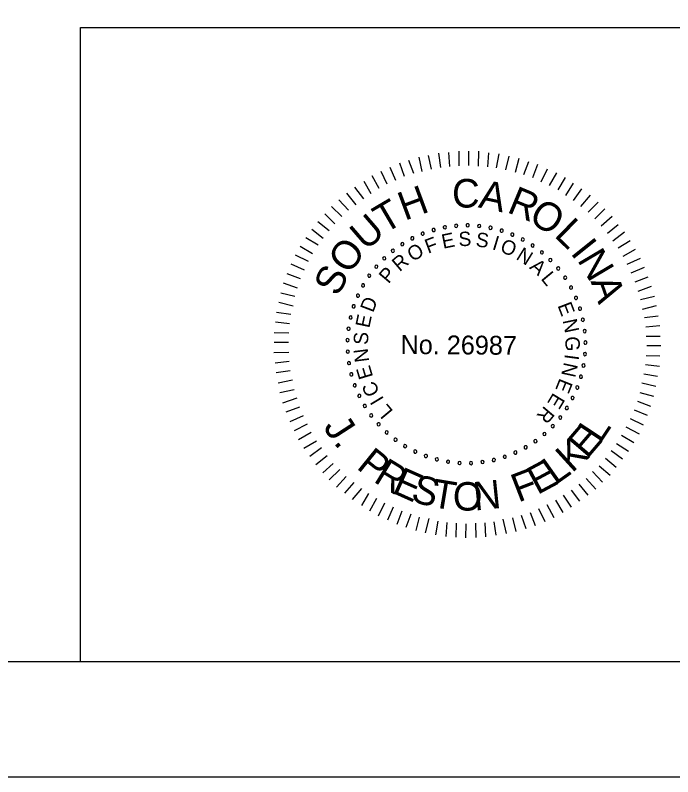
# Model space of a CAD drawing. Extents: x -383 to 3, y -322 to -94.
# Drawn here: x -215.77 to -204.37, y -187.49 to -174.28 of the extents above; entities that cross this region are included whole.
import ezdxf

# ---------------------------------------------------------------- set-up
doc = ezdxf.new("R2010")
doc.units = 0
for name, color, linetype in [('BR_BORDER LINES', 7, 'Continuous'), ('BR_TEXT', 7, 'Continuous'), ('Level 31', 7, 'Continuous')]:
    doc.layers.add(name, color=color, linetype=linetype)

msp = doc.modelspace()

# ---------------------------------------------------------------- linework, layer by layer
at = {"layer": 'BR_BORDER LINES'}
for p, q in [((-214.64, -174.489), (-193.18, -174.489)), ((-214.64, -185.489), (-214.64, -174.489)), ((-297.843, -185.489), (-163.178, -185.489))]:
    msp.add_line(p, q, dxfattribs=at)
at = {"layer": 'BR_TEXT'}
for p, q in [((-208.077, -176.892), (-208.075, -176.634)), ((-207.909, -176.883), (-207.907, -176.636)), ((-207.741, -176.895), (-207.732, -176.637)), ((-208.717, -176.986), (-208.77, -176.742)), ((-208.552, -176.946), (-208.608, -176.709)), ((-208.394, -176.917), (-208.429, -176.673)), ((-208.236, -176.901), (-208.251, -176.657)), ((-207.58, -176.906), (-207.561, -176.663)), ((-207.426, -176.925), (-207.382, -176.681)), ((-207.265, -176.957), (-207.208, -176.721)), ((-207.1, -176.999), (-207.036, -176.756)), ((-209.02, -177.076), (-209.103, -176.842)), ((-208.861, -177.026), (-208.949, -176.795)), ((-206.953, -177.042), (-206.865, -176.813)), ((-206.795, -177.095), (-206.708, -176.862)), ((-209.323, -177.211), (-209.427, -176.987)), ((-209.175, -177.144), (-209.269, -176.92)), ((-206.652, -177.165), (-206.54, -176.942)), ((-206.508, -177.234), (-206.383, -177.012)), ((-209.602, -177.377), (-209.724, -177.16)), ((-209.461, -177.282), (-209.582, -177.065)), ((-206.358, -177.308), (-206.229, -177.093)), ((-209.726, -177.462), (-209.883, -177.258)), ((-206.225, -177.405), (-206.089, -177.19)), ((-206.091, -177.492), (-205.946, -177.291)), ((-209.861, -177.564), (-210.021, -177.363)), ((-205.962, -177.596), (-205.799, -177.398)), ((-209.993, -177.662), (-210.159, -177.482)), ((-205.836, -177.696), (-205.663, -177.519)), ((-210.11, -177.771), (-210.287, -177.594)), ((-205.723, -177.807), (-205.55, -177.634)), ((-210.228, -177.894), (-210.402, -177.724)), ((-205.611, -177.932), (-205.421, -177.765)), ((-210.328, -178.02), (-210.526, -177.864)), ((-205.502, -178.06), (-205.316, -177.907)), ((-210.432, -178.153), (-210.63, -177.993)), ((-205.407, -178.194), (-205.21, -178.038)), ((-210.519, -178.269), (-210.735, -178.137)), ((-205.319, -178.312), (-205.109, -178.183)), ((-210.617, -178.416), (-210.832, -178.287)), ((-205.231, -178.46), (-205.017, -178.335)), ((-210.686, -178.552), (-210.912, -178.441)), ((-210.756, -178.699), (-210.985, -178.598)), ((-205.16, -178.598), (-204.929, -178.49)), ((-205.089, -178.746), (-204.862, -178.648)), ((-210.826, -178.853), (-211.059, -178.766)), ((-205.022, -178.901), (-204.795, -178.817)), ((-210.876, -179.014), (-211.122, -178.923)), ((-204.968, -179.063), (-204.738, -178.976)), ((-210.925, -179.158), (-211.168, -179.098)), ((-210.954, -179.326), (-211.204, -179.262)), ((-204.928, -179.207), (-204.688, -179.151)), ((-204.895, -179.376), (-204.654, -179.316)), ((-210.996, -179.47), (-211.24, -179.437)), ((-204.862, -179.52), (-204.625, -179.491)), ((-211.015, -179.634), (-211.261, -179.605)), ((-204.836, -179.685), (-204.592, -179.66)), ((-211.026, -179.792), (-211.284, -179.79)), ((-204.831, -179.843), (-204.59, -179.845)), ((-211.034, -179.957), (-211.285, -179.955)), ((-204.822, -180.008), (-204.578, -180.01)), ((-211.029, -180.129), (-211.286, -180.133)), ((-204.833, -180.18), (-204.593, -180.189)), ((-211.02, -180.283), (-211.267, -180.312)), ((-204.841, -180.334), (-204.598, -180.367)), ((-211.004, -180.448), (-211.248, -180.484)), ((-204.87, -180.499), (-204.634, -180.538)), ((-210.964, -180.606), (-211.215, -180.659)), ((-204.906, -180.656), (-204.666, -180.713)), ((-210.938, -180.775), (-211.182, -180.831)), ((-204.942, -180.824), (-204.702, -180.885)), ((-210.891, -180.923), (-211.139, -181.006)), ((-204.984, -180.971), (-204.755, -181.059)), ((-210.845, -181.077), (-211.079, -181.161)), ((-205.04, -181.125), (-204.814, -181.213)), ((-210.777, -181.226), (-211.008, -181.334)), ((-210.71, -181.37), (-210.937, -181.489)), ((-205.11, -181.272), (-204.884, -181.384)), ((-210.642, -181.519), (-210.859, -181.644)), ((-205.183, -181.416), (-204.954, -181.538)), ((-205.257, -181.563), (-205.045, -181.692)), ((-210.547, -181.667), (-210.765, -181.792)), ((-210.462, -181.784), (-210.663, -181.93)), ((-205.347, -181.71), (-205.139, -181.839)), ((-210.361, -181.919), (-210.561, -182.075)), ((-205.437, -181.826), (-205.243, -181.975)), ((-210.262, -182.054), (-210.439, -182.217)), ((-205.535, -181.959), (-205.351, -182.118)), ((-210.146, -182.158), (-210.326, -182.338)), ((-205.645, -182.092), (-205.458, -182.258)), ((-210.031, -182.279), (-210.2, -182.463)), ((-205.874, -182.313), (-205.704, -182.5)), ((-205.76, -182.194), (-205.589, -182.377)), ((-209.901, -182.383), (-210.064, -182.57)), ((-206.002, -182.415), (-205.842, -182.605)), ((-209.768, -182.487), (-209.928, -182.678)), ((-209.645, -182.574), (-209.77, -182.782)), ((-206.133, -182.517), (-205.99, -182.71)), ((-209.505, -182.664), (-209.63, -182.879)), ((-206.402, -182.69), (-206.277, -182.907)), ((-206.268, -182.602), (-206.135, -182.812)), ((-209.368, -182.744), (-209.477, -182.967)), ((-209.221, -182.814), (-209.319, -183.037)), ((-206.699, -182.835), (-206.591, -183.059)), ((-206.554, -182.768), (-206.432, -182.992)), ((-209.068, -182.884), (-209.155, -183.11)), ((-208.91, -182.933), (-209.001, -183.166)), ((-207.002, -182.949), (-206.918, -183.183)), ((-206.843, -182.902), (-206.759, -183.13)), ((-208.766, -182.983), (-208.823, -183.219)), ((-208.602, -183.011), (-208.662, -183.258)), ((-208.444, -183.057), (-208.484, -183.29)), ((-208.287, -183.076), (-208.306, -183.323)), ((-208.129, -183.087), (-208.131, -183.335)), ((-207.961, -183.099), (-207.963, -183.343)), ((-207.792, -183.09), (-207.787, -183.338)), ((-207.631, -183.081), (-207.616, -183.329)), ((-207.476, -183.065), (-207.437, -183.299)), ((-207.315, -183.022), (-207.262, -183.27)), ((-207.15, -182.996), (-207.09, -183.233))]:
    msp.add_line(p, q, dxfattribs=at)
for centre, start, end in [((-208.323, -177.957), 10.6038, 190.6038), ((-208.323, -177.957), 190.6038, 10.6038), ((-208.126, -177.93), 5.0653, 185.0653), ((-208.126, -177.93), 185.0653, 5.0653), ((-207.926, -177.923), 359.5268, 179.5268), ((-207.926, -177.923), 179.5268, 359.5268), ((-207.727, -177.934), 173.9884, 353.9884), ((-207.727, -177.934), 353.9884, 173.9884), ((-207.531, -177.965), 168.4499, 348.4499), ((-207.531, -177.965), 348.4499, 168.4499), ((-208.706, -178.067), 21.6807, 201.6807), ((-208.706, -178.067), 201.6807, 21.6807), ((-208.517, -178.003), 16.1422, 196.1422), ((-208.517, -178.003), 196.1422, 16.1422), ((-207.338, -178.015), 162.9114, 342.9114), ((-207.338, -178.015), 342.9114, 162.9114), ((-207.15, -178.083), 157.373, 337.373), ((-207.15, -178.083), 337.373, 157.373), ((-209.06, -178.248), 32.7576, 212.7576), ((-208.887, -178.149), 27.2191, 207.2191), ((-208.887, -178.149), 207.2191, 27.2191), ((-206.97, -178.169), 151.8345, 331.8345), ((-206.97, -178.169), 331.8345, 151.8345), ((-209.223, -178.364), 38.2961, 218.2961), ((-209.223, -178.364), 218.2961, 38.2961), ((-209.06, -178.248), 212.7576, 32.7576), ((-206.8, -178.272), 146.2961, 326.2961), ((-206.8, -178.272), 326.2961, 146.2961), ((-209.373, -178.495), 43.8345, 223.8345), ((-209.373, -178.495), 223.8345, 43.8345), ((-206.639, -178.39), 140.7576, 320.7576), ((-206.639, -178.39), 320.7576, 140.7576), ((-209.511, -178.639), 49.373, 229.373), ((-209.511, -178.639), 229.373, 49.373), ((-206.492, -178.524), 135.2191, 315.2191), ((-206.492, -178.524), 315.2191, 135.2191), ((-206.357, -178.671), 129.6807, 309.6807), ((-206.357, -178.671), 309.6807, 129.6807), ((-209.633, -178.796), 54.9114, 234.9114), ((-209.633, -178.796), 234.9114, 54.9114), ((-206.238, -178.831), 124.1422, 304.1422), ((-206.238, -178.831), 304.1422, 124.1422), ((-209.74, -178.964), 60.4499, 240.4499), ((-209.74, -178.964), 240.4499, 60.4499), ((-206.135, -179.001), 118.6038, 298.6038), ((-206.135, -179.001), 298.6038, 118.6038), ((-209.83, -179.142), 65.9884, 245.9884), ((-209.83, -179.142), 245.9884, 65.9884), ((-206.048, -179.181), 113.0653, 293.0653), ((-206.048, -179.181), 293.0653, 113.0653), ((-209.903, -179.328), 71.5268, 251.5268), ((-209.903, -179.328), 251.5268, 71.5268), ((-205.979, -179.368), 107.5268, 287.5268), ((-205.979, -179.368), 287.5268, 107.5268), ((-209.957, -179.52), 77.0653, 257.0653), ((-209.957, -179.52), 257.0653, 77.0653), ((-205.929, -179.561), 101.9884, 281.9884), ((-205.929, -179.561), 281.9884, 101.9884), ((-209.993, -179.716), 82.6038, 262.6038), ((-209.993, -179.716), 262.6038, 82.6038), ((-205.897, -179.758), 96.4499, 276.4499), ((-205.897, -179.758), 276.4499, 96.4499), ((-210.009, -179.914), 88.1422, 268.1422), ((-210.009, -179.914), 268.1422, 88.1422), ((-205.885, -179.957), 90.9114, 270.9114), ((-205.885, -179.957), 270.9114, 90.9114), ((-210.006, -180.114), 93.6807, 273.6807), ((-210.006, -180.114), 273.6807, 93.6807), ((-205.892, -180.156), 85.373, 265.373), ((-205.892, -180.156), 265.373, 85.373), ((-209.984, -180.312), 99.2191, 279.2191), ((-209.984, -180.312), 279.2191, 99.2191), ((-205.918, -180.353), 79.8345, 259.8345), ((-205.918, -180.353), 259.8345, 79.8345), ((-209.943, -180.507), 104.7576, 284.7576), ((-209.943, -180.507), 284.7576, 104.7576), ((-205.963, -180.548), 74.2961, 254.2961), ((-205.963, -180.548), 254.2961, 74.2961), ((-209.884, -180.697), 110.2961, 290.2961), ((-209.884, -180.697), 290.2961, 110.2961), ((-206.026, -180.737), 68.7576, 248.7576), ((-206.026, -180.737), 248.7576, 68.7576), ((-209.806, -180.881), 115.8345, 295.8345), ((-209.806, -180.881), 295.8345, 115.8345), ((-206.108, -180.918), 63.2191, 243.2191), ((-206.108, -180.918), 243.2191, 63.2191), ((-209.711, -181.056), 121.373, 301.373), ((-209.711, -181.056), 301.373, 121.373), ((-206.207, -181.092), 57.6807, 237.6807), ((-206.207, -181.092), 237.6807, 57.6807), ((-209.599, -181.221), 126.9114, 306.9114), ((-209.599, -181.221), 306.9114, 126.9114), ((-206.321, -181.255), 52.1422, 232.1422), ((-206.321, -181.255), 232.1422, 52.1422), ((-209.472, -181.375), 132.4499, 312.4499), ((-209.472, -181.375), 312.4499, 132.4499), ((-206.452, -181.406), 46.6038, 226.6038), ((-206.452, -181.406), 226.6038, 46.6038), ((-209.331, -181.515), 137.9884, 317.9884), ((-209.331, -181.515), 317.9884, 137.9884), ((-206.596, -181.543), 41.0653, 221.0653), ((-206.596, -181.543), 221.0653, 41.0653), ((-209.177, -181.642), 143.5268, 323.5268), ((-209.177, -181.642), 323.5268, 143.5268), ((-206.752, -181.667), 35.5268, 215.5268), ((-206.752, -181.667), 215.5268, 35.5268), ((-209.011, -181.753), 149.0653, 329.0653), ((-209.011, -181.753), 329.0653, 149.0653), ((-206.92, -181.774), 29.9884, 209.9884), ((-206.92, -181.774), 209.9884, 29.9884), ((-208.836, -181.847), 154.6038, 334.6038), ((-208.836, -181.847), 334.6038, 154.6038), ((-208.652, -181.924), 160.1422, 340.1422), ((-208.652, -181.924), 340.1422, 160.1422), ((-207.283, -181.938), 18.9114, 198.9114), ((-207.098, -181.865), 24.4499, 204.4499), ((-207.098, -181.865), 204.4499, 24.4499), ((-208.462, -181.983), 165.6807, 345.6807), ((-208.462, -181.983), 345.6807, 165.6807), ((-208.267, -182.023), 171.2191, 351.2191), ((-208.267, -182.023), 351.2191, 171.2191), ((-208.068, -182.045), 356.7576, 176.7576), ((-208.068, -182.045), 176.7576, 356.7576), ((-207.869, -182.047), 2.2961, 182.2961), ((-207.869, -182.047), 182.2961, 2.2961), ((-207.67, -182.029), 7.8345, 187.8345), ((-207.67, -182.029), 187.8345, 7.8345), ((-207.474, -181.993), 13.373, 193.373), ((-207.474, -181.993), 193.373, 13.373), ((-207.283, -181.938), 198.9114, 18.9114)]:
    msp.add_arc(centre, 0.028, start, end, dxfattribs=at)
at = {"layer": 'Level 31'}
msp.add_lwpolyline([(-305.176, -187.489), (-161.176, -187.489), (-161.176, -99.489), (-305.176, -99.489)], close=True, dxfattribs=at)

# ---------------------------------------------------------------- texts
at = {"layer": 'BR_TEXT'}
for s, height, rotation, p in [('C', 0.496, 359.5482, (-208.2, -177.612)), ('A', 0.496, 348.1981, (-207.755, -177.609)), ('H', 0.496, 20.3637, (-209.018, -177.846)), ('R', 0.496, 337.4344, (-207.262, -177.689)), ('T', 0.496, 30.4992, (-209.37, -178.076)), ('O', 0.496, 326.5869, (-206.893, -177.836)), ('U', 0.496, 40.8022, (-209.694, -178.375)), ('L', 0.496, 315.9488, (-206.442, -178.107)), ('E', 0.249, 11.4103, (-208.352, -178.33)), ('S', 0.249, 2.208, (-208.081, -178.286)), ('S', 0.249, 352.6608, (-207.796, -178.287)), ('O', 0.496, 52.0267, (-209.993, -178.79)), ('F', 0.249, 20.6127, (-208.613, -178.417)), ('I', 0.249, 343.1136, (-207.515, -178.335)), ('O', 0.249, 338.4392, (-207.381, -178.376)), ('I', 0.496, 308.6613, (-206.157, -178.404)), ('O', 0.249, 30.8477, (-208.882, -178.561)), ('N', 0.249, 328.2042, (-207.103, -178.501)), ('N', 0.496, 300.7037, (-206.035, -178.521)), ('R', 0.249, 40.3949, (-209.107, -178.737)), ('A', 0.249, 318.657, (-206.867, -178.662)), ('S', 0.496, 63.2511, (-210.174, -179.173)), ('P', 0.249, 49.9421, (-209.299, -178.947)), ('L', 0.249, 309.4546, (-206.668, -178.851)), ('A', 0.496, 289.4792, (-205.798, -178.894)), ('D', 0.249, 69.0364, (-209.567, -179.448)), ('E', 0.249, 291.049, (-206.372, -179.312)), ('E', 0.249, 78.2388, (-209.633, -179.715)), ('N', 0.249, 281.8466, (-206.283, -179.572)), ('S', 0.249, 87.786, (-209.656, -179.999)), ('No. 26987', 0.327, 359.5268, (-209.092, -180.153)), ('G', 0.249, 272.2995, (-206.237, -179.853)), ('N', 0.249, 97.3332, (-209.632, -180.283)), ('I', 0.249, 262.4084, (-206.238, -180.149)), ('N', 0.249, 257.7339, (-206.256, -180.287)), ('E', 0.249, 106.5355, (-209.564, -180.549)), ('E', 0.249, 248.1867, (-206.328, -180.563)), ('C', 0.249, 116.4266, (-209.444, -180.819)), ('E', 0.249, 238.9844, (-206.44, -180.814)), ('I', 0.249, 121.1011, (-209.372, -180.939)), ('L', 0.249, 129.9595, (-209.209, -181.147)), ('R', 0.249, 229.782, (-206.591, -181.044)), ('J', 0.494, 302.9559, (-210.441, -181.421)), ('E', 0.494, 49.3639, (-205.857, -181.989)), ('L', 0.494, 56.4247, (-205.627, -181.718)), ('K', 0.494, 42.3031, (-206.118, -182.229)), ('.', 0.494, 309.3974, (-210.264, -181.693)), ('P', 0.494, 321.1035, (-209.871, -182.13)), ('R', 0.494, 328.5359, (-209.578, -182.362)), ('E', 0.494, 28.1814, (-206.719, -182.605)), ('L', 0.494, 35.2422, (-206.407, -182.436)), ('E', 0.494, 335.9684, (-209.257, -182.555)), ('F', 0.494, 21.1206, (-207.05, -182.735)), ('S', 0.494, 343.0292, (-208.932, -182.698)), ('T', 0.494, 350.4617, (-208.573, -182.804)), ('O', 0.494, 358.1419, (-208.192, -182.863)), ('N', 0.494, 5.8221, (-207.805, -182.872))]:
    msp.add_text(s, height=height, rotation=rotation, dxfattribs=at).set_placement(p)

doc.saveas('drawing.dxf')
